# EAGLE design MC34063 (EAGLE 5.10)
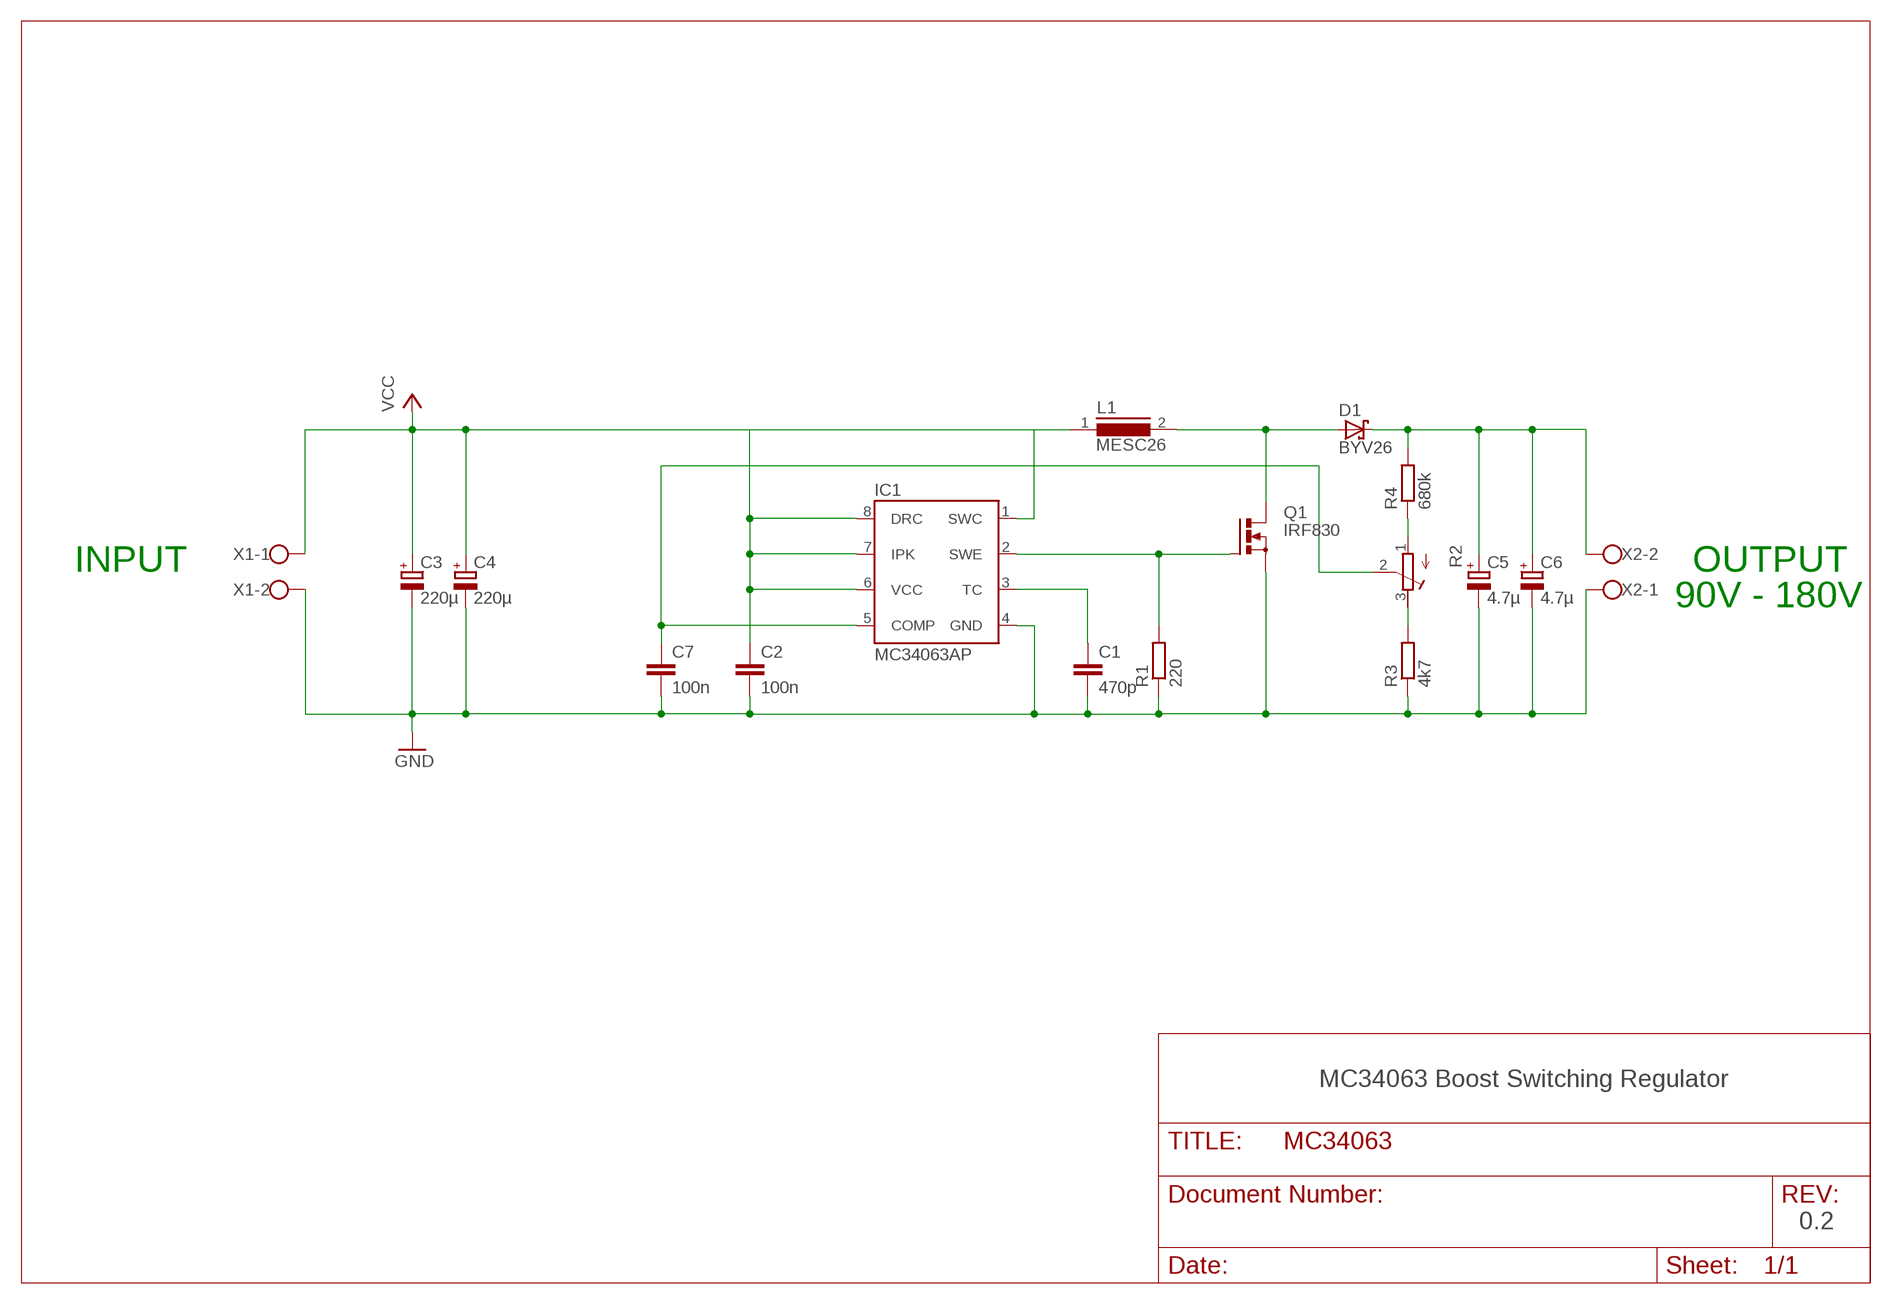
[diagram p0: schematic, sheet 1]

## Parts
C1  470p  C-EU025-030X050  [C025-030X050]
C2  100n  C-EU025-030X050  [C025-030X050]
C3  220µ  CPOL-EUE2.5-6  [E2,5-6]
C4  220µ  CPOL-EUE2.5-6  [E2,5-6]
C5  4.7µ  CPOL-EUE3.5-8  [E3,5-8]
C6  4.7µ  CPOL-EUE3.5-8  [E3,5-8]
C7  100n  C-EU025-030X050  [C025-030X050]
D1  BYV26  BYV10  [DO41-10]
IC1  MC34063AP  [DIL-08]
L1  MESC26  [MESC26]
Q1  IRF830  PMOSFET_NTO220BV  [TO220BV]
R1  220  R-EU_0207/7  [0207/7]
R2  R-TRIMM3296W  [RTRIM3296W]
R3  4k7  R-EU_0207/7  [0207/7]
R4  680k  R-EU_0207/7  [0207/7]
X1  W237-102  [W237-102]
X2  W237-102  [W237-102]

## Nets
GND: C1.2 C2.2 C3.- C4.- C5.- C6.- C7.2 IC1.4(GND) Q1.S R1.1 R3.1 X1.2 X2.1
N$1: IC1.2(SWE) Q1.G R1.2
N$2: C1.1 IC1.3(TC)
N$3: D1.A L1.2 Q1.D
N$4: C5.+ C6.+ D1.C R4.2 X2.2
N$5: R2.1(E) R4.1
N$6: R2.3(A) R3.2
N$7: C7.1 IC1.5(COMP) R2.2(S)
VCC: C2.1 C3.+ C4.+ IC1.1(SWC) IC1.6(VCC) IC1.7(IPK) IC1.8(DRC) L1.1 X1.1

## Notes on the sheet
- INPUT | OUTPUT
- 90V - 180V
- MC34063 Boost Switching Regulator
- 0.2

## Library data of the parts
C1 C2 C7 = rcl:C-EU: CAPACITOR, European symbol
C3-C6 = rcl:CPOL-EU: POLARIZED CAPACITOR, European symbol
D1 = diode:BYV10: DIODE
IC1 = v-reg-3:MC34063A: 1.5A Step-Up/Down/Inverting Switching Regulator NPN Darlington Switch, Vin 3V to 40V, Current Limiter Input, adjustable Frequency up to 100kHz
L1 = inductors:MESC26: INDUCTOR
Q1 = transistor-power:PMOSFET_N: Power MOSFET N-Channel
R1 R3 R4 = rcl:R-EU_: RESISTOR, European symbol
R2 = rcl:R-TRIMM: Trimm resistor
X1 X2 = con-wago-500:W237-102: WAGO SCREW CLAMP

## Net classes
0 default: width 0.254 mm
1 Ground: width 0.1 mm, drill 0.2 mm

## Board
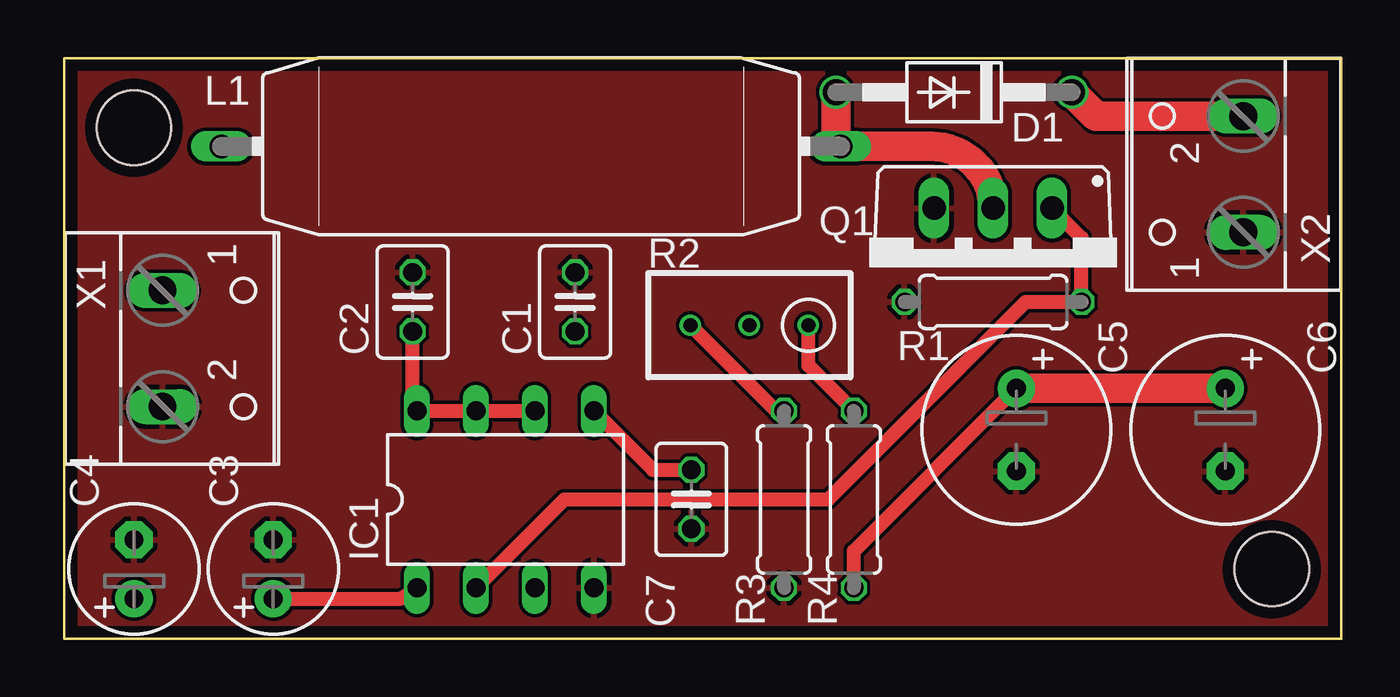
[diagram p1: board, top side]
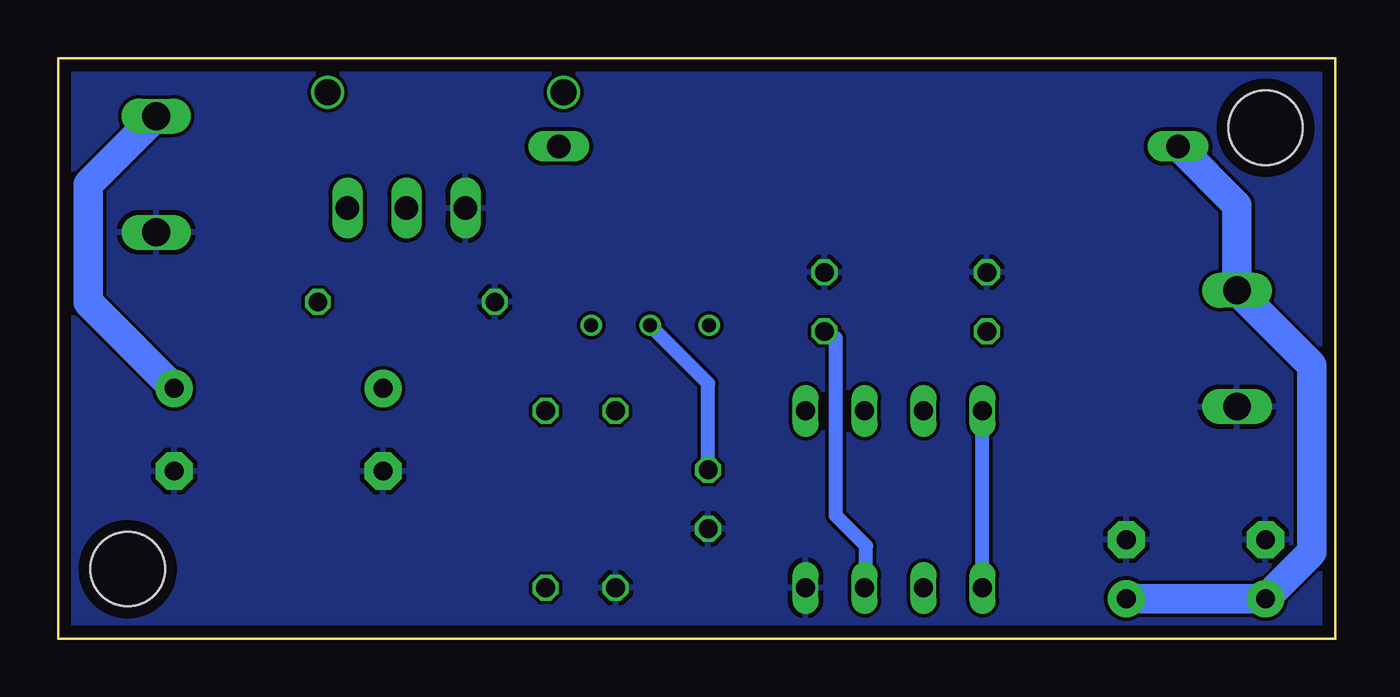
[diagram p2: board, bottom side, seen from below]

Size 55 x 25 mm. Coordinates in mm from the lower left corner, seen from the top.
Outline: 0,0 55,0 55,25 0,25 0,0
Copper layers (1*16): Top 0.035mm / dielectric 1.5mm / Bottom 0.035mm
Design rules "PCB-POOL *": minimum track width 6mil, minimum drill 12mil, track to track 6mil, track to pad 6mil, pad to pad 6mil, via to via 6mil, smd to smd 6mil, copper to edge 20mil, drill to drill 8mil, minimum pad ring 6mil, minimum via ring 6mil, stop-mask expansion 3mil, vias tented up to drill 0mil, thermal gap 8mil
Holes 3.2 mm at 3,22 52,3

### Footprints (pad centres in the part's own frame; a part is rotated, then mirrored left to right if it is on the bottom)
C025-030X050 = drill 0.813 octagon: 1 -1.27,0; 2 1.27,0
E2,5-6 = drill 0.813 pad 1.6 round: + -1.27,0 | drill 0.813 pad 1.6 octagon: - 1.27,0
E3,5-8 = drill 0.813 pad 1.6 round: + -1.778,0 | drill 0.813 pad 1.6 octagon: - 1.778,0
DO41-10 = drill 1.118 round: A 5.08,0; C -5.08,0
DIL-08 = drill 0.813 long: 1 -3.81,-3.81; 2 -1.27,-3.81; 3 1.27,-3.81; 4 3.81,-3.81; 5 3.81,3.81; 6 1.27,3.81; 7 -1.27,3.81; 8 -3.81,3.81
MESC26 = drill 1.016 long: 1 -13.335,0; 2 13.335,0
TO220BV = drill 1.016 long: D 0,-2.54; G -2.54,-2.54; S 2.54,-2.54
0207/7 = drill 0.813 octagon: 1 -3.81,0; 2 3.81,0
RTRIM3296W = drill 0.61 round: 1 0,-2.54; 2 0,0; 3 0,2.54
W237-102 = drill 1.194 long: 1 -2.5,-1.27; 2 2.5,-1.27

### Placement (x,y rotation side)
C1  22,14.5 90 top
C2  15,14.5 90 top
C3  9,3 90 top
C4  3,3 90 top
C5  41,9 270 top
C6  50,9 270 top
C7  27,6 270 top
D1  38.32,23.53 180 top
IC1  19,6 0 top
L1  20.1,21.2 0 top
Q1  40,16 180 top
R1  40,14.5 0 top
R2  29.5,13.5 90 top
R3  31,6 90 top
R4  34,6 270 top
X1  5.5,12.5 270 top
X2  49.5,20 90 top

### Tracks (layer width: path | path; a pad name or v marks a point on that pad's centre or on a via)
GND
  pour Top: 0,0 0,25 55,25 55,0
  pour Bottom: 0,0 0,25 55,25 55,0
N$1
  Top 0.61: IC1.2 21.54,6 32.9,6 41.4,14.5 R1.2 43.81,17.27 Q1.G
N$2
  Bottom 0.61: C1.1 21.5,12.94 21.5,5.3 20.2,4 20.2,2.34 IC1.3
N$3
  Top 1.27: D1.A 33.24,21.4 L1.2 37.34,21.2 arc-90 Q1.D
N$4
  Top 0.61: C5.+ 34,3.78 R4.2
  Top 1.27: D1.C 44.42,22.5 X2.2 | C5.+ C6.+
  Bottom 1.27: C6.+ 53.7,14.48 53.7,19.57 X2.2
N$5
  Top 0.61: R2.1 32.04,11.77 R4.1
N$6
  Top 0.61: R2.3 30.65,9.81 R3.2
N$7
  Top 0.61: IC1.5 25.35,7.27 C7.1
  Bottom 0.61: C7.1 27,11 R2.2
VCC
  Top 0.61: C3.+ 14.51,1.73 IC1.1 | IC1.6 IC1.7 IC1.8 15,10 C2.1
  Bottom 0.61: IC1.1 IC1.8 15.06,9.96
  Bottom 1.27: L1.1 4.23,18.66 X1.1 1,11.77 1,3.73 C4.+ C3.+

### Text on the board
Measures: 50.0 mm | 66.0 mm
tDocu: + | INPUT | OUTPUT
